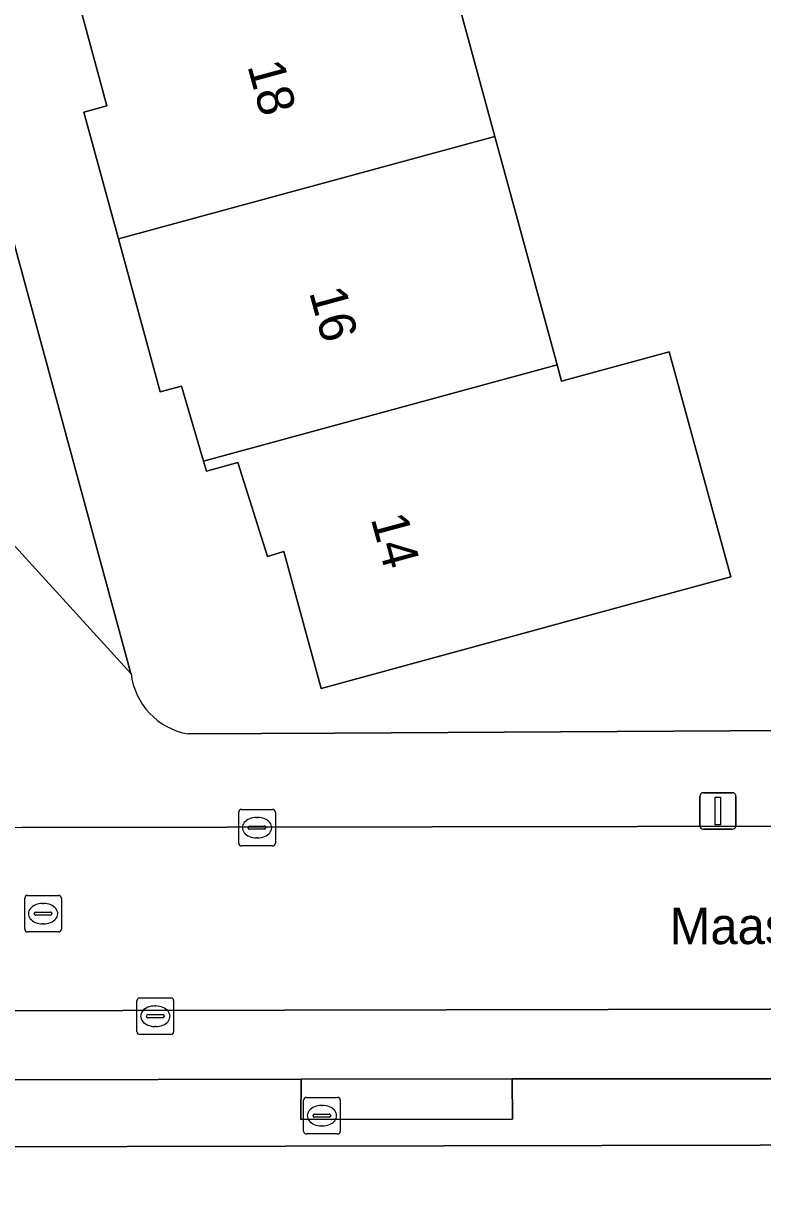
# Model space of a CAD drawing. Extents: x 160732 to 162107, y 387428 to 388479.
# Drawn here: x 161086.66 to 161106.86, y 387842.58 to 387874.51 of the extents above; entities that cross this region are included whole.
import ezdxf

# ---------------------------------------------------------------- set-up
doc = ezdxf.new("R2010")
doc.units = 0
for name, color, linetype in [('IMGEO_Brandkraan', 7, 'Continuous'), ('IMGEO_Erf', 7, 'Continuous'), ('IMGEO_Kolk', 7, 'Continuous'), ('IMGEO_Lichtmast', 7, 'Continuous'), ('IMGEO_Muur', 7, 'Continuous'), ('IMGEO_Openbare_ruimte_label', 7, 'Continuous'), ('IMGEO_Pand', 7, 'Continuous'), ('IMGEO_Pand_nummerreeks', 7, 'Continuous'), ('IMGEO_Parkeervlak_open', 7, 'Continuous'), ('IMGEO_Rijbaan_lokaal_open', 7, 'Continuous'), ('IMGEO_Rioolput', 7, 'Continuous'), ('IMGEO_Voetpad_open', 7, 'Continuous')]:
    doc.layers.add(name, color=color, linetype=linetype)

msp = doc.modelspace()

# ---------------------------------------------------------------- linework, layer by layer
at = {"layer": 'IMGEO_Brandkraan'}
for p, q in [((161094.391, 387845.152), (161095.243, 387845.152)), ((161094.316, 387844.226), (161094.316, 387845.078)), ((161094.804, 387844.932), (161094.829, 387844.932)), ((161095.317, 387845.078), (161095.317, 387844.226)), ((161094.575, 387844.646), (161094.575, 387844.658)), ((161095.013, 387844.609), (161094.615, 387844.609)), ((161094.618, 387844.695), (161095.016, 387844.695)), ((161095.059, 387844.658), (161095.059, 387844.646)), ((161094.827, 387844.372), (161094.802, 387844.372)), ((161095.243, 387844.152), (161094.391, 387844.152))]:
    msp.add_line(p, q, dxfattribs=at)
for points in [[(161094.391, 387845.152), (161095.243, 387845.152)], [(161094.316, 387844.226), (161094.316, 387845.078)], [(161095.317, 387845.078), (161095.317, 387844.226)], [(161095.243, 387844.152), (161094.391, 387844.152)]]:
    msp.add_lwpolyline(points, dxfattribs=at)
for centre, radius, start, end in [((161094.393, 387845.076), 0.0765, 91.552, 178.448), ((161094.393, 387845.076), 0.0765, 91.552, 178.448), ((161095.241, 387845.076), 0.0765, 1.552, 88.448), ((161095.241, 387845.076), 0.0765, 1.552, 88.448), ((161094.615, 387844.655), 0.0403, 85.8775, 175.7526), ((161094.612, 387844.645), 0.0366, 178.938, 274.7102), ((161095.016, 387844.652), 0.043, 264.8664, 352.4533), ((161095.02, 387844.657), 0.0386, 1.7309, 96.639), ((161094.393, 387844.228), 0.0765, 181.552, 268.448), ((161094.393, 387844.228), 0.0765, 181.552, 268.448), ((161095.241, 387844.228), 0.0765, 271.552, 358.448), ((161095.241, 387844.228), 0.0765, 271.552, 358.448)]:
    msp.add_arc(centre, radius, start, end, dxfattribs=at)
for centre, major_axis, ratio, start_param, end_param in [((161094.803, 387844.652), (-0.387, 0.002), 0.722429, 4.712389, 7.853982), ((161094.828, 387844.652), (-0.39, 0.002), 0.717154, 1.570796, 4.712389)]:
    msp.add_ellipse(centre, major_axis=major_axis, ratio=ratio, start_param=start_param, end_param=end_param, dxfattribs=at)
at = {"layer": 'IMGEO_Erf'}
for points in [[(161072.769, 387920.054), (161072.802, 387918.618), (161089.6, 387856.737)], [(161098.629, 387874.761), (161099.54, 387871.419), (161101.242, 387865.174), (161101.363, 387864.731), (161104.305, 387865.534), (161105.984, 387859.378), (161103.041, 387858.576), (161094.797, 387856.328), (161093.78, 387860.077), (161093.325, 387859.934), (161092.517, 387862.502), (161091.66, 387862.271), (161091.581, 387862.542), (161090.983, 387864.593), (161090.393, 387864.439), (161089.258, 387868.617), (161088.316, 387872.083), (161088.944, 387872.253), (161088.205, 387874.975)], [(161091.158, 387855.088), (161095.167, 387855.112), (161109.047, 387855.187), (161112.79, 387855.204), (161152.485, 387855.226)], [(161154.339, 387843.946), (161067.871, 387843.768), (161067.395, 387843.044), (161067.316, 387840.96), (161072.889, 387840.898), (161072.873, 387842.027), (161080.561, 387842.057), (161080.565, 387840.938), (161083.641, 387840.952), (161086.529, 387840.966), (161086.523, 387842.066), (161094.21, 387842.083), (161094.214, 387840.964), (161097.314, 387840.957), (161100.175, 387840.95), (161100.174, 387842.098), (161107.877, 387842.112)]]:
    msp.add_lwpolyline(points, dxfattribs=at)
msp.add_arc((161091.489, 387856.961), 1.902, 186.7614, 259.9879, dxfattribs=at)
at = {"layer": 'IMGEO_Kolk'}
for p, q in [((161092.543, 387852.099), (161092.543, 387852.951)), ((161092.618, 387853.025), (161093.47, 387853.025)), ((161093.031, 387852.805), (161093.056, 387852.805)), ((161093.544, 387852.951), (161093.544, 387852.099)), ((161092.802, 387852.519), (161092.802, 387852.531)), ((161093.24, 387852.482), (161092.842, 387852.482)), ((161092.845, 387852.568), (161093.243, 387852.568)), ((161093.286, 387852.531), (161093.286, 387852.519)), ((161093.054, 387852.245), (161093.029, 387852.245)), ((161093.47, 387852.025), (161092.618, 387852.025)), ((161089.764, 387846.945), (161089.764, 387847.797)), ((161089.839, 387847.871), (161090.691, 387847.871)), ((161090.765, 387847.797), (161090.765, 387846.945)), ((161090.023, 387847.365), (161090.023, 387847.377)), ((161090.066, 387847.414), (161090.464, 387847.414)), ((161090.252, 387847.651), (161090.277, 387847.651)), ((161090.507, 387847.377), (161090.507, 387847.365)), ((161090.461, 387847.328), (161090.063, 387847.328)), ((161090.275, 387847.091), (161090.25, 387847.091)), ((161090.691, 387846.871), (161089.839, 387846.871))]:
    msp.add_line(p, q, dxfattribs=at)
for points in [[(161092.543, 387852.099), (161092.543, 387852.951)], [(161092.618, 387853.025), (161093.47, 387853.025)], [(161093.544, 387852.951), (161093.544, 387852.099)], [(161093.47, 387852.025), (161092.618, 387852.025)], [(161089.764, 387846.945), (161089.764, 387847.797)], [(161089.839, 387847.871), (161090.691, 387847.871)], [(161090.765, 387847.797), (161090.765, 387846.945)], [(161090.691, 387846.871), (161089.839, 387846.871)]]:
    msp.add_lwpolyline(points, dxfattribs=at)
for centre, radius, start, end in [((161092.62, 387852.949), 0.0765, 91.552, 178.448), ((161092.62, 387852.949), 0.0765, 91.552, 178.448), ((161093.468, 387852.949), 0.0765, 1.552, 88.448), ((161093.468, 387852.949), 0.0765, 1.552, 88.448), ((161092.842, 387852.528), 0.0403, 85.8775, 175.7526), ((161092.839, 387852.518), 0.0366, 178.938, 274.7102), ((161093.243, 387852.525), 0.043, 264.8664, 352.4533), ((161093.247, 387852.53), 0.0386, 1.7309, 96.639), ((161092.62, 387852.101), 0.0765, 181.552, 268.448), ((161092.62, 387852.101), 0.0765, 181.552, 268.448), ((161093.468, 387852.101), 0.0765, 271.552, 358.448), ((161093.468, 387852.101), 0.0765, 271.552, 358.448), ((161089.841, 387847.795), 0.0765, 91.552, 178.448), ((161089.841, 387847.795), 0.0765, 91.552, 178.448), ((161090.689, 387847.795), 0.0765, 1.552, 88.448), ((161090.689, 387847.795), 0.0765, 1.552, 88.448), ((161090.063, 387847.374), 0.0403, 85.8775, 175.7526), ((161090.06, 387847.364), 0.0366, 178.938, 274.7102), ((161090.464, 387847.371), 0.043, 264.8664, 352.4533), ((161090.468, 387847.376), 0.0386, 1.7309, 96.639), ((161089.841, 387846.947), 0.0765, 181.552, 268.448), ((161089.841, 387846.947), 0.0765, 181.552, 268.448), ((161090.689, 387846.947), 0.0765, 271.552, 358.448), ((161090.689, 387846.947), 0.0765, 271.552, 358.448)]:
    msp.add_arc(centre, radius, start, end, dxfattribs=at)
for centre, major_axis, ratio, start_param, end_param in [((161093.03, 387852.525), (-0.387, 0.002), 0.722429, 4.712389, 7.853982), ((161093.055, 387852.525), (-0.39, 0.002), 0.717154, 1.570796, 4.712389), ((161090.251, 387847.371), (-0.387, 0.002), 0.722429, 4.712389, 7.853982), ((161090.276, 387847.371), (-0.39, 0.002), 0.717154, 1.570796, 4.712389)]:
    msp.add_ellipse(centre, major_axis=major_axis, ratio=ratio, start_param=start_param, end_param=end_param, dxfattribs=at)
at = {"layer": 'IMGEO_Lichtmast'}
for p, q in [((161105.239, 387853.481), (161106.029, 387853.481)), ((161106.029, 387853.481), (161105.239, 387853.481)), ((161105.139, 387852.581), (161105.139, 387853.381)), ((161105.139, 387853.381), (161105.139, 387852.581)), ((161106.129, 387853.381), (161106.129, 387852.581)), ((161106.129, 387852.581), (161106.129, 387853.381)), ((161106.029, 387852.481), (161105.239, 387852.481)), ((161105.239, 387852.481), (161106.029, 387852.481))]:
    msp.add_line(p, q, dxfattribs=at)
msp.add_lwpolyline([(161105.559, 387853.356), (161105.709, 387853.356), (161105.709, 387852.606), (161105.559, 387852.606), (161105.559, 387853.356)], dxfattribs=at)
for centre, start, end in [((161105.239, 387853.381), 90, 180), ((161105.239, 387853.381), 90, 180), ((161106.029, 387853.381), 0, 90), ((161106.029, 387853.381), 360, 90), ((161105.239, 387852.581), 180, 270), ((161105.239, 387852.581), 180, 270), ((161106.029, 387852.581), 270, 0), ((161106.029, 387852.581), 270, 0)]:
    msp.add_arc(centre, 0.1, start, end, dxfattribs=at)
at = {"layer": 'IMGEO_Muur'}
msp.add_lwpolyline([(161109.047, 387855.187), (161095.167, 387855.112)], dxfattribs=at)
at = {"layer": 'IMGEO_Pand'}
for points in [[(161098.629, 387874.761), (161102.536, 387875.826), (161101.761, 387878.669), (161097.854, 387877.604), (161088.205, 387874.975), (161088.944, 387872.253), (161088.316, 387872.083), (161089.258, 387868.617), (161099.54, 387871.419)], [(161101.242, 387865.174), (161099.54, 387871.419), (161089.258, 387868.617), (161090.393, 387864.439), (161090.983, 387864.593), (161091.581, 387862.542)], [(161101.242, 387865.174), (161091.581, 387862.542), (161091.66, 387862.271), (161092.517, 387862.502), (161093.325, 387859.934), (161093.78, 387860.077), (161094.797, 387856.328), (161103.041, 387858.576), (161105.984, 387859.378), (161104.305, 387865.534), (161101.363, 387864.731)]]:
    msp.add_lwpolyline(points, close=True, dxfattribs=at)
at = {"layer": 'IMGEO_Parkeervlak_open'}
for points in [[(161111.468, 387847.576), (161071.693, 387847.488)], [(161074.718, 387845.605), (161094.25, 387845.653), (161100.017, 387845.66), (161108.662, 387845.661)]]:
    msp.add_lwpolyline(points, dxfattribs=at)
at = {"layer": 'IMGEO_Rijbaan_lokaal_open'}
msp.add_lwpolyline([(161069.255, 387847.491), (161071.476, 387847.488), (161071.693, 387847.488), (161111.468, 387847.576), (161112.55, 387847.578), (161147.649, 387847.619), (161148.329, 387847.635), (161148.349, 387852.658), (161113.214, 387852.617), (161112.762, 387852.617), (161109.039, 387852.562), (161086.621, 387852.533), (161064.109, 387852.517)], dxfattribs=at)
at = {"layer": 'IMGEO_Rioolput'}
for p, q in [((161086.698, 387849.749), (161086.698, 387850.601)), ((161086.773, 387850.675), (161087.625, 387850.675)), ((161087.699, 387850.601), (161087.699, 387849.749)), ((161087.186, 387850.455), (161087.211, 387850.455)), ((161086.957, 387850.169), (161086.957, 387850.181)), ((161087.395, 387850.132), (161086.997, 387850.132)), ((161087, 387850.218), (161087.398, 387850.218)), ((161087.441, 387850.181), (161087.441, 387850.169)), ((161087.625, 387849.675), (161086.773, 387849.675)), ((161087.209, 387849.895), (161087.184, 387849.895))]:
    msp.add_line(p, q, dxfattribs=at)
for points in [[(161086.698, 387849.749), (161086.698, 387850.601)], [(161086.773, 387850.675), (161087.625, 387850.675)], [(161087.699, 387850.601), (161087.699, 387849.749)], [(161087.625, 387849.675), (161086.773, 387849.675)]]:
    msp.add_lwpolyline(points, dxfattribs=at)
for centre, radius, start, end in [((161086.775, 387850.599), 0.0765, 91.552, 178.448), ((161086.775, 387850.599), 0.0765, 91.552, 178.448), ((161087.623, 387850.599), 0.0765, 1.552, 88.448), ((161087.623, 387850.599), 0.0765, 1.552, 88.448), ((161086.997, 387850.178), 0.0403, 85.8775, 175.7526), ((161086.994, 387850.168), 0.0366, 178.938, 274.7102), ((161087.398, 387850.175), 0.043, 264.8664, 352.4533), ((161087.402, 387850.18), 0.0386, 1.7309, 96.639), ((161086.775, 387849.751), 0.0765, 181.552, 268.448), ((161086.775, 387849.751), 0.0765, 181.552, 268.448), ((161087.623, 387849.751), 0.0765, 271.552, 358.448), ((161087.623, 387849.751), 0.0765, 271.552, 358.448)]:
    msp.add_arc(centre, radius, start, end, dxfattribs=at)
for centre, major_axis, ratio, start_param, end_param in [((161087.185, 387850.175), (-0.387, 0.002), 0.722429, 4.712389, 7.853982), ((161087.21, 387850.175), (-0.39, 0.002), 0.717154, 1.570796, 4.712389)]:
    msp.add_ellipse(centre, major_axis=major_axis, ratio=ratio, start_param=start_param, end_param=end_param, dxfattribs=at)
at = {"layer": 'IMGEO_Voetpad_open'}
for points in [[(161065.263, 387934.732), (161065.347, 387922.488), (161065.355, 387921.319), (161065.436, 387909.613), (161065.212, 387908.27), (161072.472, 387908.32), (161085.132, 387861.629), (161089.6, 387856.737), (161072.802, 387918.618)], [(161089.6, 387856.737), (161085.132, 387861.629), (161067.757, 387861.58), (161061.226, 387861.549), (161061.23, 387857.692), (161061.248, 387851.8), (161062.997, 387853.117), (161064.094, 387853.137), (161064.093, 387858.233)], [(161152.485, 387855.226), (161112.79, 387855.204), (161109.047, 387855.187), (161095.167, 387855.112), (161091.158, 387855.088)], [(161086.621, 387852.533), (161109.039, 387852.562), (161109.019, 387853.689), (161112.762, 387853.691), (161112.762, 387852.617), (161113.214, 387852.617), (161148.349, 387852.658), (161150.774, 387852.713)], [(161071.693, 387847.488), (161071.476, 387847.488), (161071.474, 387846.396), (161067.871, 387843.768), (161154.339, 387843.946), (161155.133, 387845.919)], [(161108.662, 387845.661), (161100.017, 387845.66), (161100.026, 387844.558), (161094.24, 387844.546), (161094.25, 387845.653), (161074.718, 387845.605)]]:
    msp.add_lwpolyline(points, dxfattribs=at)
msp.add_lwpolyline([(161100.017, 387845.66), (161094.25, 387845.653), (161094.24, 387844.546), (161100.026, 387844.558)], close=True, dxfattribs=at)
msp.add_arc((161091.489, 387856.961), 1.902, 186.7614, 259.9879, dxfattribs=at)

# ---------------------------------------------------------------- texts
at = {"layer": 'IMGEO_Openbare_ruimte_label'}
msp.add_text('Maaseikstraat', height=1, rotation=0.1719, dxfattribs=at).set_placement((161104.317, 387849.337))
at = {"layer": 'IMGEO_Pand_nummerreeks'}
for s, p in [('18', (161092.775, 387873.35)), ('16', (161094.461, 387867.163)), ('14', (161096.147, 387860.973))]:
    msp.add_text(s, height=1, rotation=285.245, dxfattribs=at).set_placement(p)

doc.saveas('drawing.dxf')
